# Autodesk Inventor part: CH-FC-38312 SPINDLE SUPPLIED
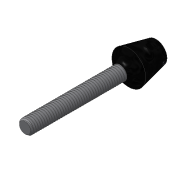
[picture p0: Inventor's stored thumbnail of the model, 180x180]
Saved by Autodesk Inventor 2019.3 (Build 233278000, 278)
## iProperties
Created: 2012-09
Part Number: CH-FC-38312 SPINDLE SUPPLIED
Material: Ogólny
Document SubType Name: Modeling
Designer: CADENGINEERING4
Density: 1 g/cm^3
Appearance: Domyślna
Author: CADENGINEERING4
Revision Number: ÈÎºÎ
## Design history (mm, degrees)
feature "NONE"
node "Bryła1"
